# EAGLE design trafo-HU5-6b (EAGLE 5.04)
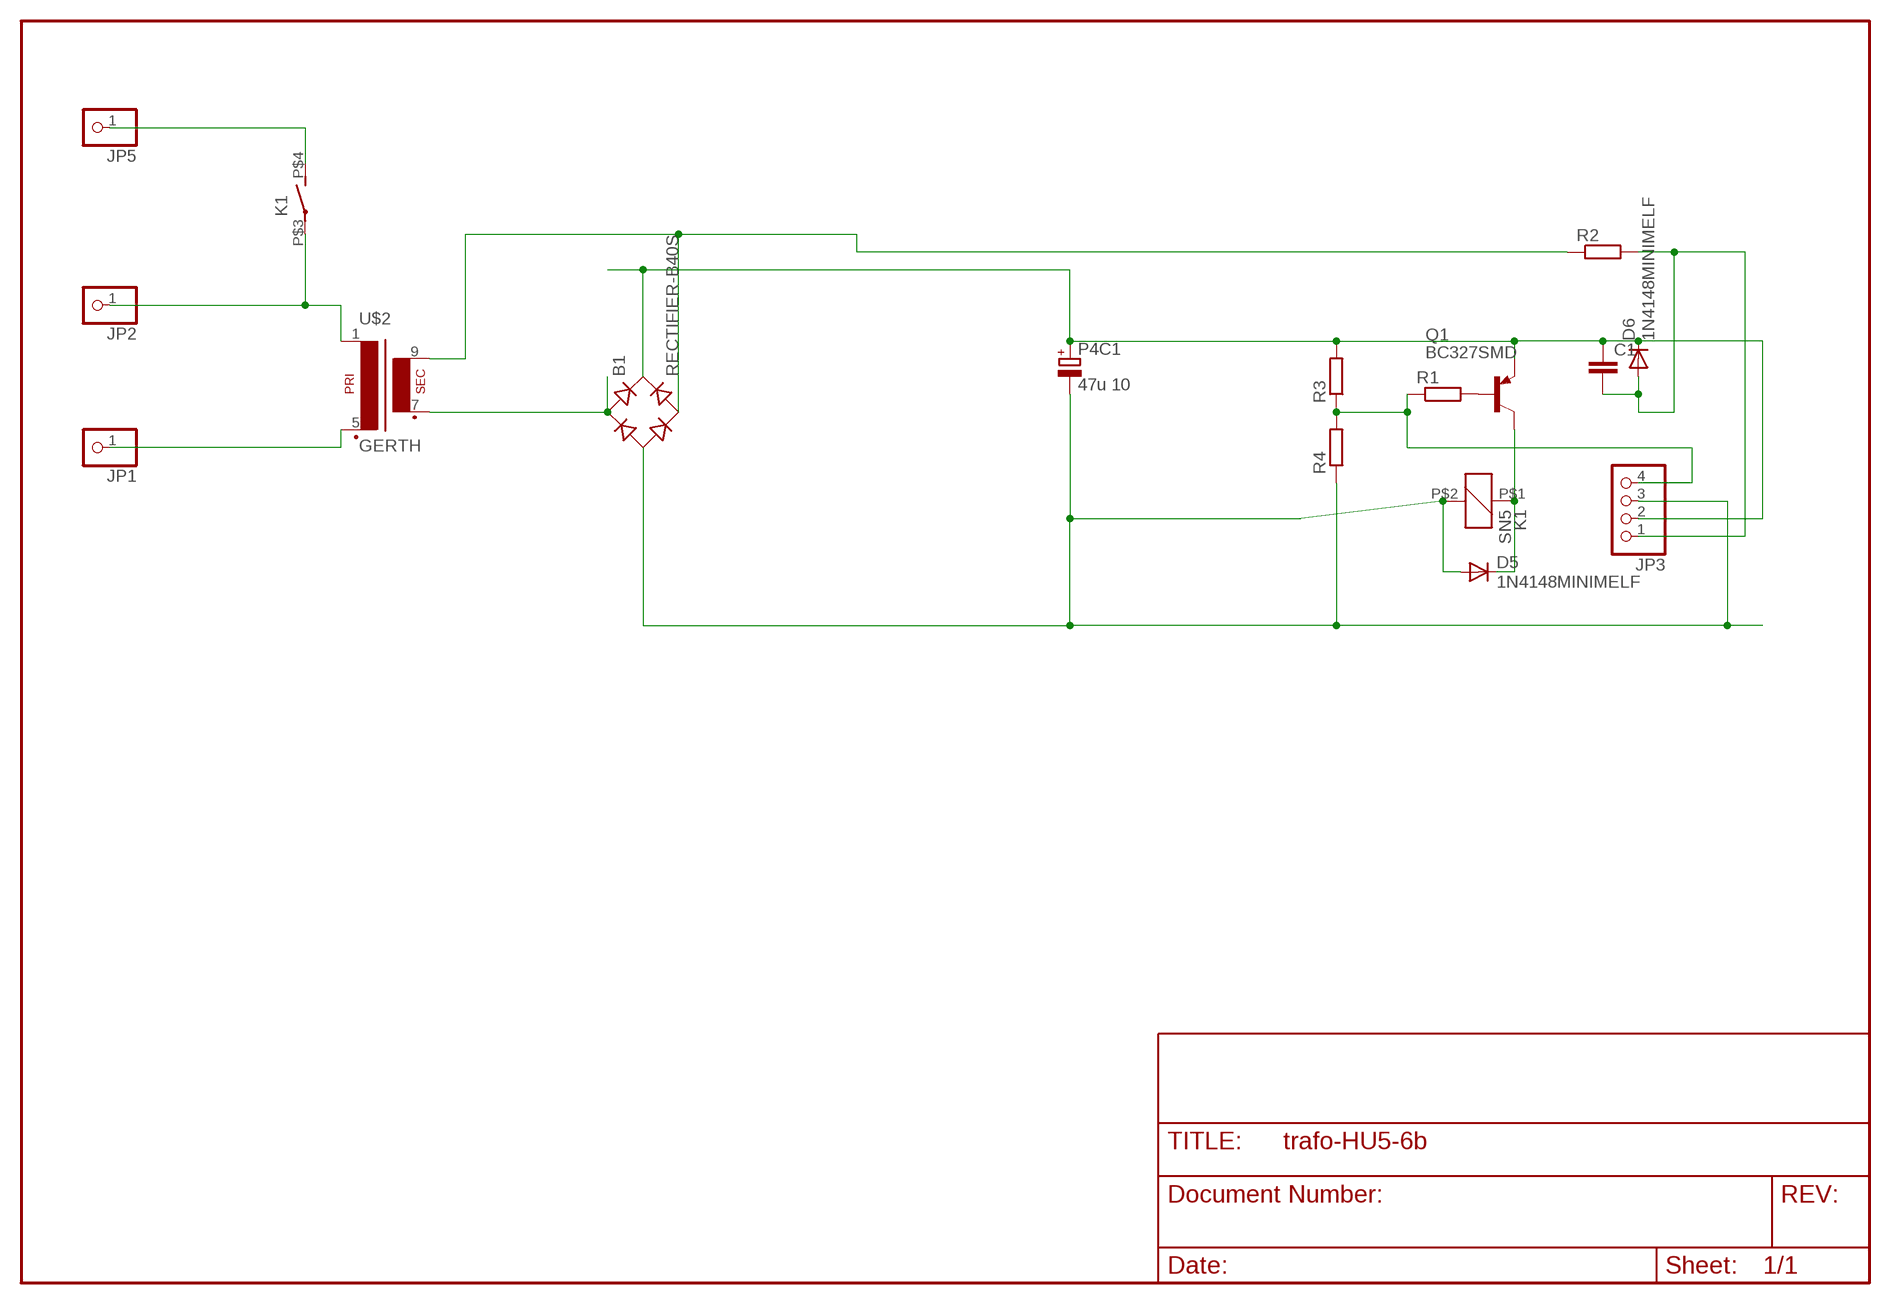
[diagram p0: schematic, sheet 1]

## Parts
B1  RECTIFIER-B40S  [B40S]
C1  C-EUC1206  [C1206]
D5  1N4148MINIMELF  [MINIMELF]
D6  1N4148MINIMELF  [MINIMELF]
JP1  PINHD-1X1  [1X01]
JP2  PINHD-1X1  [1X01]
JP3  PINHD-1X4  [1X04]
JP5  PINHD-1X1  [1X01]
K1  SN5  [HU]
P4C1  47u 10  CPOL-EUE2-5  [E2-5]
Q1  BC327SMD  [SOT23-BEC]
R1  R-EU_R0805  [R0805]
R2  R-EU_R1206  [R1206]
R3  R-EU_R0805  [R0805]
R4  R-EU_R0805  [R0805]
U$2  GERTH  [150.06]

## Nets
N$1: JP2.1 K1.P$3(2:P) U$2.1
N$2: B1.+ C1.1 D6.C JP3.2 P4C1.+ Q1.E R3.2
N$3: B1.- D5.A JP3.3 K1.P$2 P4C1.- R4.1
N$4: JP5.1 K1.P$4(2:S)
N$5: JP1.1 U$2.5(P2)
N$6: B1.AC1 U$2.7(S3)
N$7: B1.AC2 R2.1 U$2.9(S4)
N$8: Q1.B R1.2
N$9: C1.2 D6.A JP3.1 R2.2
N$10: JP3.4 R1.1 R3.1 R4.2
N$11: D5.C K1.P$1 Q1.C

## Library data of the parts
B1 = rectifier:RECTIFIER-: Rectifier
C1 = rcl-2:C-EU: CAPACITOR, European symbol
D5 D6 = diode-1:1N4148: DIODE
JP1 JP2 JP5 = pinhead(2):PINHD-1X1: PIN HEADER
JP3 = pinhead(2):PINHD-1X4: PIN HEADER
K1 = relay:SN*: Slim PCB Relay 1 pole 6 A SCHRACK Source: http://www.schrack.com/.. 5815.pdf
P4C1 = rcl:CPOL-EU: POLARIZED CAPACITOR, European symbol
Q1 = transistor-pnp:BC327*: PNP Transistror
R1-R4 = rcl-2:R-EU_: RESISTOR, European symbol
U$2 = trafo:GERTH

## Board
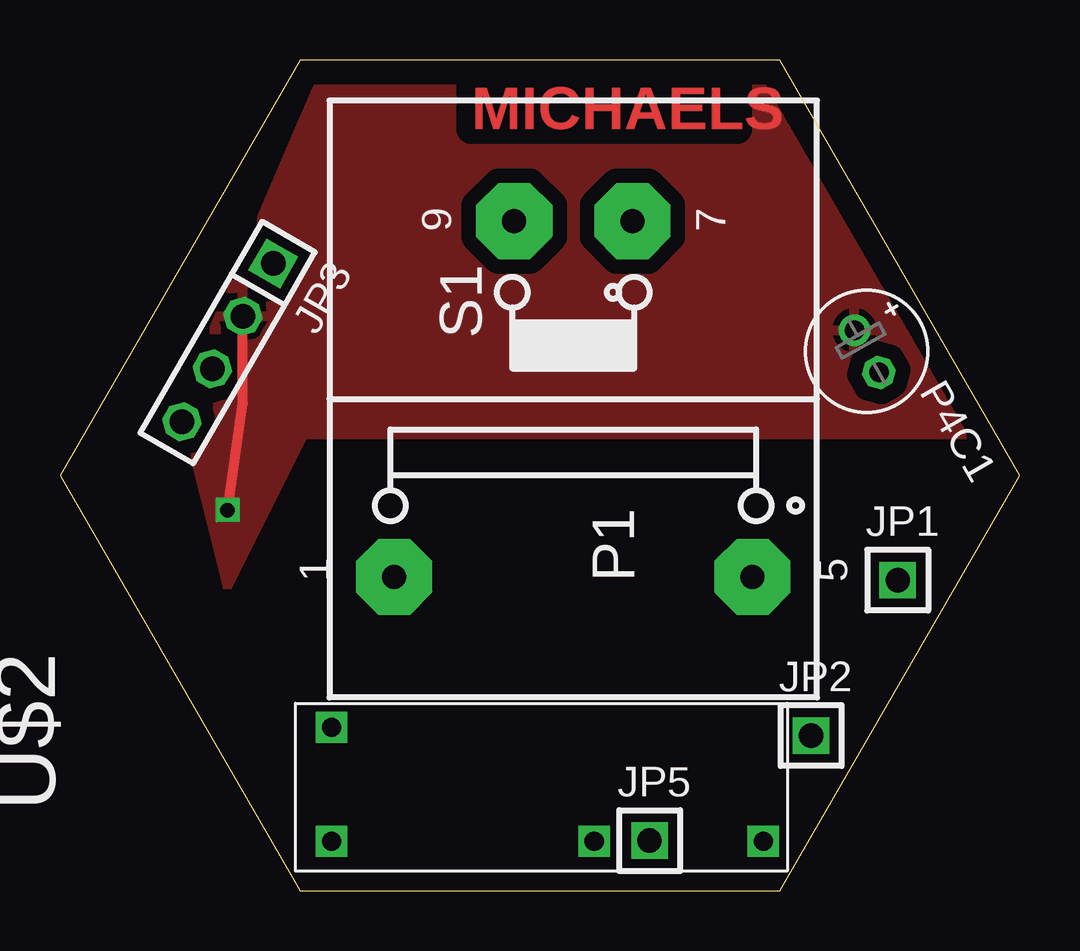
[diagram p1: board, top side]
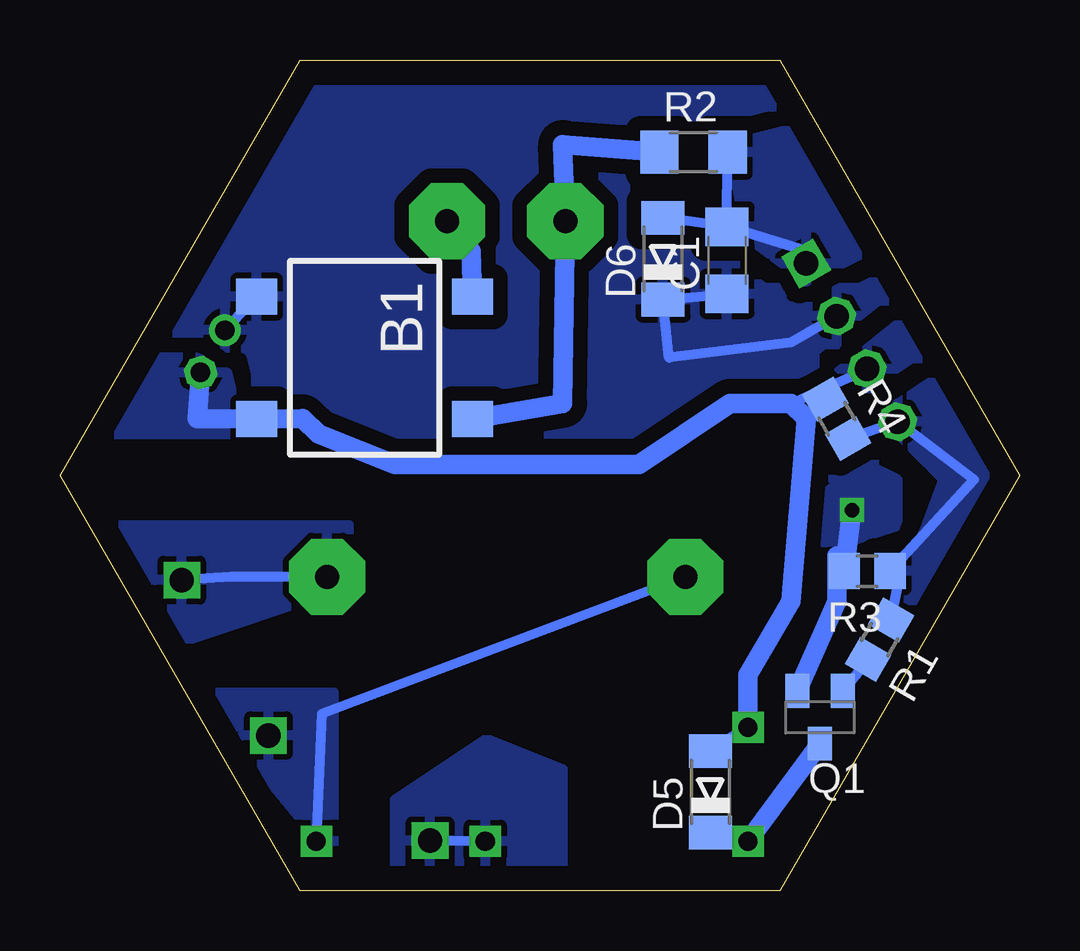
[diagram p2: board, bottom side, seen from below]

Size 40 x 34.64 mm. Coordinates in mm from the lower left corner, seen from the top.
Outline: 10,0 30,0 40,17.32 30,34.64 10,34.64 0,17.32 10,0
Copper layers (1*16): Top 0.035mm / dielectric 1.5mm / Bottom 0.035mm
Design rules "default": minimum track width 10mil, minimum drill 24mil, track to track 8mil, track to pad 8mil, pad to pad 8mil, via to via 8mil, smd to smd 8mil, copper to edge 40mil, drill to drill 8mil, minimum pad ring 10mil, minimum via ring 8mil, stop-mask expansion 4mil, vias tented up to drill 0mil, thermal gap 10mil

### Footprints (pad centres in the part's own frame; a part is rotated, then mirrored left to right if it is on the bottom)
B40S = smd 1.5 x 1.7: + -2.55,-4.5; - 2.55,-4.5; AC1 -2.55,4.5; AC2 2.55,4.5
C1206 = smd 1.6 x 1.8: 1 -1.4,0; 2 1.4,0
MINIMELF = smd 1.4 x 1.8: A 1.7,0; C -1.7,0
1X01 = drill 1.016 square: 1 0,0
1X04 = drill 1.016 square: 1 -3.81,0 | drill 1.016 octagon: 2 -1.27,0; 3 1.27,0; 4 3.81,0
HU = drill 0.8 square: P$1 2.25,-9; P$2 -2.5,-9; P$3 2.25,9; P$4 2.25,1.95
E2-5 = drill 0.813 pad 1.27 round: + -1.016,0 | drill 0.813 pad 1.27 octagon: - 1.016,0
SOT23-BEC = smd 1 x 1.4: B -0.95,-1.1; C 0,1.1; E 0.95,-1.1
R0805 = smd 1.3 x 1.5: 1 -0.95,0; 2 0.95,0
R1206 = smd 1.6 x 1.803: 1 -1.422,0; 2 1.422,0
150.06 = drill 1 pad 3.175 octagon: 1 -7.417,7.468; 5 -7.417,-7.468; 7 7.417,-2.464; 9 7.417,2.464

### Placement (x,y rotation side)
B1  27.3,22.23 270 bottom
C1  12.19,26.29 90 bottom
D5  12.89,4.13 90 bottom
D6  14.86,26.35 90 bottom
JP1  34.92,12.95 0 top
JP2  31.31,6.48 0 top
JP3  6.99,22.86 240 top
JP5  24.57,2.1 0 top
K1  20.32,4.32 270 top
P4C1  33.63,22.49 300 top
Q1  8.32,7.24 180 bottom
R1  5.83,10.48 240 bottom
R2  13.59,30.8 0 bottom
R3  6.35,13.34 180 bottom
R4  7.62,19.68 300 bottom
U$2  21.4,20.51 90 top

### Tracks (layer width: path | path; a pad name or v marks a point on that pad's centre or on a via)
N$1
  Bottom 0.406: U$2.1 29.09,7.38 K1.P$3
  pour Bottom (isolate 0.61, rank 2): 28.57,1.27 28.57,8.26 34.29,8.26
N$2  (via drill 0.6)
  Top 0.406: v6.99,15.88 7.62,20.32 JP3.2
  Bottom 0.406: B1.+ P4C1.+ | 7.62,13.97 R3.2 | JP3.2 9.53,22.86 14.61,22.23 D6.C C1.1
  Bottom 0.813: Q1.E 7.62,12.06 7.62,13.97 | R3.2 v6.99,15.88
  pour Top (isolate 0.61, rank 3): 5.08,20.32 6.99,12.7 10.16,19.05 38.1,19.05 29.21,33.66 10.79,33.66
  pour Bottom (isolate 0.61, rank 3): 3.17,21.59 6.99,16.51 10.16,19.05 38.1,19.05 29.21,33.66 10.79,33.66
  pour Bottom (isolate 0.61, rank 2): 6.35,17.78 8.26,16.51 8.26,13.97 6.99,14.61 5.08,15.24 5.08,17.14
N$3
  Bottom 0.406: D5.A 12.06,6.35 K1.P$2 | 9.53,20.32 JP3.3 | 8.89,19.68 R4.1
  Bottom 0.813: K1.P$2 11.32,9 9.53,12.06 8.89,19.68 9.53,20.32 12.06,20.32 15.88,17.78 26.04,17.78 29.21,19.05 29.89,19.68 B1.- 34.29,19.68 P4C1.-
  pour Bottom (isolate 0.305): 34.29,22.23 36.2,22.23 38.1,19.05 32.38,19.05 33.02,21.59
  pour Bottom (isolate 0.61, rank 2): 4.45,24.13 7.62,21.59 7.62,20.95 5.71,20.95 3.81,22.23
N$4
  Bottom 0.406: K1.P$4 JP5.1
  pour Bottom: 26.04,0.64 26.04,3.81 22.23,6.35 19.05,5.08 19.05,0.64
N$5
  Bottom 0.406: U$2.5 32.88,13.09 JP1.1
  pour Bottom (isolate 0.61, rank 2): 27.94,15.24 38.1,15.24 35.56,10.16 27.94,12.7
N$6
  Bottom 0.813: B1.AC1 22.86,26.67 U$2.7
N$7
  Bottom 0.813: R2.1 19.05,31.11 U$2.9 19.05,20.32 B1.AC2
N$8
  Bottom 0.406: R1.2 Q1.B
N$9
  Bottom 0.406: D6.A 13.97,27.94 C1.2 | 8.89,26.67 C1.2 | C1.2 R2.2
  pour Bottom (isolate 0.305): 6.35,26.67 9.53,31.75 12.06,31.11 11.43,27.3 8.89,25.4
N$10
  Bottom 0.406: R1.1 5.08,12.7 R3.1 1.91,17.14 JP3.4 R4.2
  pour Bottom (isolate 0.61): 5.08,20.32 3.17,21.59 1.27,17.14 4.45,11.43 5.08,12.06 3.17,17.14 5.08,19.05
N$11
  Bottom 0.406: K1.P$1 D5.C
  Bottom 0.813: K1.P$1 Q1.C

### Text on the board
Top: MICHAELS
